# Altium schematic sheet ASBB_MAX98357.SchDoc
size A4
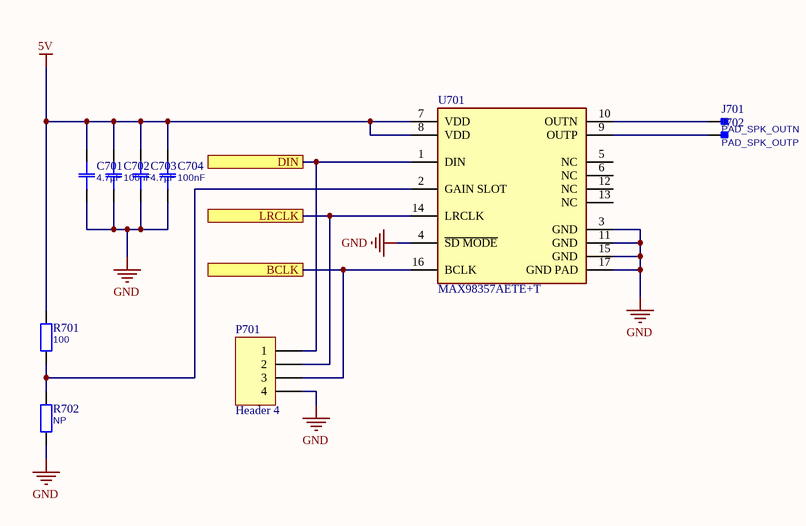
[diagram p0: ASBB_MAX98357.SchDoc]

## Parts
C701  4.7µF  [0603]
C702  100nF  [0603]
C703  4.7µF  [0603]
C704  100nF  [0603]
J701  PAD_SPK_OUTN  [PIN1]
J702  PAD_SPK_OUTP  [PIN1]
P701  Header 4  [HDR1X4]
R701  100  [0603]
R702  NP  [0603]
U701  Part Number: MAX98357AETE+T  [Maxim_Electronics_21-0896_0]  (hidden comment: IC_Maxim_Electronics_MAX98357AETE+T_eec)

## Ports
BCLK, DIN, LRCLK

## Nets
5V: C701.2 C702.2 C703.2 C704.2 R701.2 U701.7(VDD) U701.8(VDD)
GND: C701.1 C702.1 C703.1 C704.1 P701.4 R702.1 U701.3(GND) U701.4(~{SD_MODE}) U701.11(GND) U701.15(GND) U701.17(GND_PAD)
BCLK: P701.3 U701.16(BCLK) ; port BCLK
DIN: P701.1 U701.1(DIN) ; port DIN
LRCLK: P701.2 U701.14(LRCLK) ; port LRCLK
NetJ701_1: J701.1 U701.10(OUTN)
NetJ702_1: J702.1 U701.9(OUTP)
NetR701_1: R701.1 R702.2 U701.2(GAIN_SLOT)

Not connected (* = marked no-connect by the designer): U701 5(NC) 6(NC) 12(NC) 13(NC)

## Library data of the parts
C701-C704 = Capacitor
J701 J702 = Pad 1 Pin: Pad, 1 Pin
P701 = Header 4: Header, 4-Pin
R701 R702 = Resistor
U701 = IC_Maxim_Electronics_MAX98357AETE+T_eec: IC Amplifier IC 2-Channel (Stereo) Class D 16-TQFN (3x3); Manufacturer: Maxim Electronics; Mfg Package Ident: 21-0896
